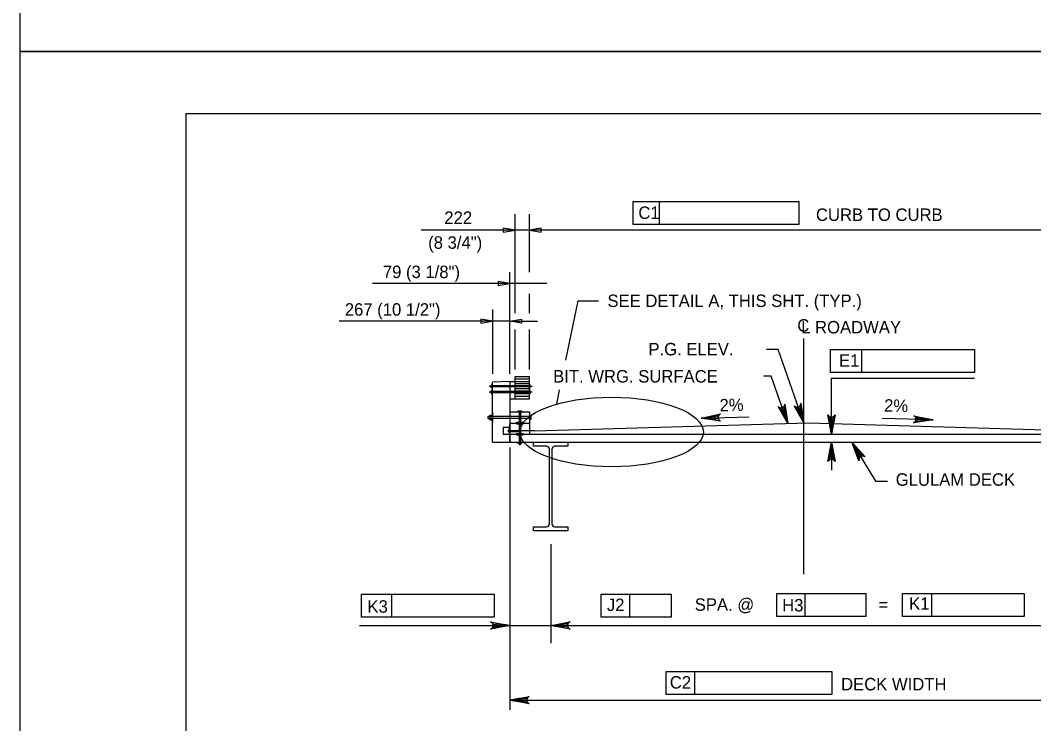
# Model space of a CAD drawing. Extents: x 638175 to 640495, y 294277 to 298435.
# Drawn here: x 638435.5 to 638679.7, y 296491.5 to 296661 of the extents above; entities that cross this region are included whole.
import ezdxf

# ---------------------------------------------------------------- set-up
doc = ezdxf.new("R2010")
doc.units = 0
for name, color, linetype in [('2', 7, 'Continuous'), ('3', 7, 'Continuous'), ('4', 7, 'Continuous'), ('6', 7, 'Continuous'), ('PLT-BNDY', 7, 'Continuous')]:
    doc.layers.add(name, color=color, linetype=linetype)

msp = doc.modelspace()

# ---------------------------------------------------------------- linework, layer by layer
at = {"layer": '2'}
for p, q in [((638475.46, 296074.46), (638475.46, 296638.46)), ((638475.46, 296638.46), (639261.46, 296638.46)), ((638554.69, 296590.38), (638554.69, 296614.24)), ((638558.16, 296600.26), (638558.16, 296614.24)), ((638560.6, 296610.39), (638532.11, 296610.39)), ((638686.45, 296610.39), (638559.36, 296610.39)), ((638553.45, 296575.77), (638553.45, 296600.26)), ((638562.36, 296597.55), (638520.38, 296597.55)), ((638558.16, 296590.38), (638558.16, 296595.03)), ((638549.28, 296591.29), (638549.28, 296575.77)), ((638553.45, 296588.49), (638512.31, 296588.49)), ((638553.45, 296588.49), (638560.11, 296588.49)), ((638554.69, 296576.86), (638554.69, 296586.46)), ((638558.16, 296576.86), (638558.16, 296586.46)), ((638624.32, 296527.56), (638624.32, 296584.32)), ((638554.69, 296569.78), (638554.69, 296575.14)), ((638554.69, 296575.14), (638558.16, 296575.14)), ((638554.69, 296574.55), (638558.16, 296574.55)), ((638558.16, 296569.78), (638558.16, 296575.14)), ((638630.96, 296574.77), (638665.42, 296574.77)), ((638630.96, 296561.25), (638630.96, 296574.77)), ((638548.75, 296572.88), (638548.77, 296572.91)), ((638548.75, 296572.88), (638548.75, 296572.63)), ((638548.75, 296572.63), (638548.77, 296572.61)), ((638548.95, 296572.91), (638548.77, 296572.91)), ((638548.95, 296572.61), (638548.77, 296572.61)), ((638548.95, 296572.93), (638548.95, 296572.59)), ((638548.95, 296572.93), (638548.95, 296572.59)), ((638548.99, 296572.99), (638549.19, 296572.99)), ((638548.99, 296572.87), (638549.19, 296572.87)), ((638548.99, 296572.64), (638549.19, 296572.64)), ((638548.99, 296572.53), (638549.19, 296572.53)), ((638549.19, 296572.17), (638549.19, 296573.36)), ((638549.19, 296573.36), (638549.28, 296573.36)), ((638549.19, 296572.53), (638549.19, 296572.99)), ((638549.28, 296572.17), (638549.19, 296572.17)), ((638549.19, 296572.17), (638549.19, 296572.17)), ((638549.19, 296570.77), (638549.19, 296571.97)), ((638549.19, 296571.97), (638549.28, 296571.97)), ((638553.45, 296573.95), (638549.28, 296573.76)), ((638549.28, 296559.29), (638549.28, 296573.76)), ((638558.16, 296572.91), (638549.28, 296572.91)), ((638558.16, 296572.62), (638549.28, 296572.62)), ((638549.28, 296572.17), (638549.28, 296572.17)), ((638553.45, 296573.95), (638554.69, 296573.95)), ((638553.45, 296573.95), (638553.45, 296566.61)), ((638554.69, 296573.95), (638558.16, 296573.95)), ((638558.16, 296573.36), (638554.69, 296573.36)), ((638558.16, 296572.17), (638554.69, 296572.17)), ((638548.75, 296571.5), (638548.77, 296571.52)), ((638548.75, 296571.5), (638548.75, 296571.25)), ((638548.75, 296571.25), (638548.77, 296571.22)), ((638548.95, 296571.52), (638548.77, 296571.52)), ((638548.95, 296571.22), (638548.77, 296571.22)), ((638548.95, 296571.54), (638548.95, 296571.2)), ((638548.95, 296571.54), (638548.95, 296571.2)), ((638548.99, 296571.6), (638549.19, 296571.6)), ((638548.99, 296571.48), (638549.19, 296571.48)), ((638548.99, 296571.25), (638549.19, 296571.25)), ((638548.99, 296571.14), (638549.19, 296571.14)), ((638549.19, 296571.14), (638549.19, 296571.6)), ((638549.28, 296570.77), (638549.19, 296570.77)), ((638549.19, 296570.77), (638549.19, 296570.77)), ((638558.16, 296571.52), (638549.28, 296571.52)), ((638558.16, 296571.22), (638549.28, 296571.22)), ((638549.28, 296570.77), (638549.28, 296570.77)), ((638553.45, 296569.78), (638558.16, 296569.78)), ((638558.16, 296571.57), (638554.69, 296571.57)), ((638558.16, 296570.98), (638554.69, 296570.98)), ((638554.69, 296570.38), (638558.16, 296570.38)), ((638555.83, 296558.78), (638555.83, 296566.96)), ((638548.15, 296565.47), (638548.2, 296565.51)), ((638548.15, 296565.47), (638548.15, 296565.07)), ((638548.15, 296565.07), (638548.2, 296565.02)), ((638548.6, 296565.51), (638548.2, 296565.51)), ((638548.2, 296565.02), (638548.6, 296565.02)), ((638548.6, 296564.86), (638548.6, 296565.68)), ((638548.6, 296565.51), (638548.6, 296565.51)), ((638548.69, 296565.82), (638549.18, 296565.82)), ((638548.69, 296565.54), (638549.18, 296565.54)), ((638548.69, 296565), (638549.18, 296565)), ((638548.7, 296564.72), (638549.18, 296564.72)), ((638549.18, 296566.46), (638549.18, 296564.08)), ((638549.28, 296566.46), (638549.18, 296566.46)), ((638549.18, 296565.82), (638549.18, 296564.72)), ((638549.28, 296565.54), (638549.18, 296565.54)), ((638549.28, 296565), (638549.18, 296565)), ((638549.28, 296566.46), (638549.28, 296564.08)), ((638558.21, 296565.51), (638549.28, 296565.51)), ((638558.21, 296565.02), (638549.28, 296565.02)), ((638553.45, 296566.61), (638553.45, 296563.93)), ((638553.45, 296566.61), (638558.21, 296566.61)), ((638555.68, 296566.61), (638555.68, 296559.29)), ((638555.98, 296566.61), (638555.98, 296559.29)), ((638558.21, 296566.61), (638558.21, 296563.93)), ((638599.57, 296565.13), (638611.11, 296565.43)), ((638655.43, 296564.69), (638643.19, 296565.03)), ((638549.18, 296564.08), (638549.28, 296564.08)), ((638551.86, 296562.84), (638551.86, 296561.25)), ((638553.45, 296562.84), (638551.86, 296562.84)), ((638553.21, 296562.24), (638553.06, 296562.24)), ((638553.06, 296562.24), (638553.06, 296561.85)), ((638553.21, 296562.34), (638553.26, 296562.34)), ((638553.21, 296562.34), (638553.21, 296561.74)), ((638553.26, 296562.84), (638553.26, 296561.25)), ((638553.26, 296562.16), (638555.38, 296562.16)), ((638553.45, 296563.93), (638553.45, 296561.25)), ((638553.45, 296563.93), (638558.21, 296563.93)), ((638558.21, 296562.06), (638553.45, 296562.06)), ((638555.04, 296564.13), (638555.04, 296563.73)), ((638555.04, 296564.13), (638556.62, 296564.13)), ((638555.04, 296563.73), (638556.62, 296563.73)), ((638555.59, 296562.04), (638555.38, 296562.16)), ((638555.59, 296562.04), (638555.38, 296561.91)), ((638556.62, 296564.13), (638556.62, 296563.73)), ((638558.21, 296563.93), (638558.21, 296561.25)), ((638559.41, 296562.06), (638558.21, 296562.06)), ((638551.86, 296561.25), (638553.45, 296561.25)), ((638553.21, 296561.85), (638553.06, 296561.85)), ((638553.21, 296561.74), (638553.26, 296561.74)), ((638553.26, 296561.91), (638555.38, 296561.91)), ((638553.45, 296561.25), (638553.45, 296559.29)), ((638555.04, 296561.45), (638555.04, 296561.05)), ((638555.04, 296561.45), (638556.62, 296561.45)), ((638555.04, 296561.05), (638556.62, 296561.05)), ((638556.62, 296561.45), (638556.62, 296561.05)), ((638553.45, 296558.01), (638553.45, 296494.83)), ((638555.23, 296559.29), (638555.23, 296559.29)), ((638555.23, 296559.29), (638555.23, 296559.19)), ((638555.23, 296559.2), (638555.23, 296559.2)), ((638555.23, 296559.19), (638556.43, 296559.19)), ((638555.6, 296558.99), (638555.6, 296559.19)), ((638555.65, 296559.29), (638555.65, 296559.19)), ((638556, 296558.96), (638555.66, 296558.96)), ((638555.68, 296558.96), (638555.68, 296558.78)), ((638555.7, 296558.76), (638555.68, 296558.78)), ((638555.7, 296558.93), (638555.95, 296558.93)), ((638555.7, 296558.91), (638555.95, 296558.91)), ((638555.7, 296558.88), (638555.95, 296558.88)), ((638555.7, 296558.86), (638555.95, 296558.86)), ((638555.7, 296558.83), (638555.95, 296558.83)), ((638555.7, 296558.8), (638555.95, 296558.8)), ((638555.7, 296558.78), (638555.95, 296558.78)), ((638555.95, 296558.76), (638555.7, 296558.76)), ((638555.72, 296558.99), (638555.72, 296559.19)), ((638555.95, 296558.99), (638555.95, 296559.19)), ((638555.95, 296558.76), (638555.98, 296558.78)), ((638555.98, 296558.96), (638555.98, 296558.78)), ((638556, 296559.29), (638556, 296559.19)), ((638556.06, 296558.99), (638556.06, 296559.19)), ((638556.43, 296559.19), (638556.43, 296559.29)), ((638630.98, 296559.29), (638630.98, 296552.6)), ((638563.3, 296534.79), (638563.3, 296512.32)), ((638563.3, 296521.08), (638563.3, 296510.92)), ((638517.21, 296515.17), (638553.45, 296515.17)), ((638553.45, 296515.17), (638688.41, 296515.17)), ((638553.45, 296497.2), (638695.18, 296497.2))]:
    msp.add_line(p, q, dxfattribs=at)
for points in [[(638551.86, 296610.86), (638551.86, 296609.92), (638554.69, 296610.39)], [(638550.62, 296598.02), (638550.62, 296597.07), (638553.45, 296597.55)], [(638546.45, 296588.96), (638546.45, 296588.01), (638549.28, 296588.49)], [(638556.29, 296588.96), (638556.29, 296588.01), (638553.45, 296588.49)], [(638602.94, 296564.74), (638602.92, 296565.69), (638600.09, 296565.14)], [(638651.34, 296565.28), (638651.32, 296564.34), (638654.16, 296564.73)], [(638631.43, 296564.25), (638630.49, 296564.25), (638630.96, 296561.42)], [(638630.51, 296556.36), (638631.45, 296556.36), (638630.98, 296559.2)], [(638566.13, 296515.64), (638566.13, 296514.7), (638563.3, 296515.17)], [(638556.08, 296496.76), (638556.08, 296497.63), (638553.45, 296497.2)]]:
    msp.add_lwpolyline(points, close=True, dxfattribs=at)
for points in [[(638620.45, 296563.82), (638618.08, 296567.93), (638618.43, 296567.67), (638618.79, 296567.6), (638619.1, 296567.65), (638619.38, 296567.81), (638619.61, 296568.08), (638619.73, 296568.51), (638620.45, 296563.82), (638619.61, 296568.08), (638619.38, 296567.81), (638620.45, 296563.82), (638619.1, 296567.65), (638618.79, 296567.6), (638620.45, 296563.82), (638618.43, 296567.67)], [(638624.3, 296563.99), (638621.93, 296568.1), (638622.28, 296567.84), (638622.64, 296567.77), (638622.95, 296567.82), (638623.23, 296567.98), (638623.46, 296568.25), (638623.58, 296568.68), (638624.3, 296563.99), (638623.46, 296568.25), (638623.23, 296567.98), (638624.3, 296563.99), (638622.95, 296567.82), (638622.64, 296567.77), (638624.3, 296563.99), (638622.28, 296567.84)], [(638599.57, 296565.13), (638604.2, 296566.12), (638603.85, 296565.87), (638603.67, 296565.55), (638603.63, 296565.24), (638603.69, 296564.92), (638603.88, 296564.62), (638604.25, 296564.38), (638599.57, 296565.13), (638603.88, 296564.62), (638603.69, 296564.92), (638599.57, 296565.13), (638603.63, 296565.24), (638603.67, 296565.55), (638599.57, 296565.13), (638603.85, 296565.87)], [(638630.96, 296561.25), (638630.09, 296565.91), (638630.33, 296565.55), (638630.65, 296565.37), (638630.96, 296565.31), (638631.27, 296565.37), (638631.58, 296565.55), (638631.83, 296565.91), (638630.96, 296561.25), (638631.58, 296565.55), (638631.27, 296565.37), (638630.96, 296561.25), (638630.96, 296565.31), (638630.65, 296565.37), (638630.96, 296561.25), (638630.33, 296565.55)], [(638655.43, 296564.69), (638650.74, 296563.95), (638651.11, 296564.19), (638651.3, 296564.49), (638651.37, 296564.8), (638651.32, 296565.12), (638651.15, 296565.44), (638650.79, 296565.7), (638655.43, 296564.69), (638651.15, 296565.44), (638651.32, 296565.12), (638655.43, 296564.69), (638651.37, 296564.8), (638651.3, 296564.49), (638655.43, 296564.69), (638651.11, 296564.19)], [(638630.98, 296559.29), (638631.85, 296554.63), (638631.61, 296554.98), (638631.29, 296555.17), (638630.98, 296555.22), (638630.67, 296555.17), (638630.36, 296554.98), (638630.11, 296554.63), (638630.98, 296559.29), (638630.36, 296554.98), (638630.67, 296555.17), (638630.98, 296559.29), (638630.98, 296555.22), (638631.29, 296555.17), (638630.98, 296559.29), (638631.61, 296554.98)], [(638635.88, 296559.29), (638639.06, 296555.77), (638638.66, 296555.94), (638638.3, 296555.94), (638638, 296555.82), (638637.76, 296555.61), (638637.59, 296555.29), (638637.57, 296554.85), (638635.88, 296559.29), (638637.59, 296555.29), (638637.76, 296555.61), (638635.88, 296559.29), (638638, 296555.82), (638638.3, 296555.94), (638635.88, 296559.29), (638638.66, 296555.94)], [(638553.45, 296515.17), (638548.79, 296514.3), (638549.15, 296514.55), (638549.33, 296514.86), (638549.39, 296515.17), (638549.33, 296515.48), (638549.15, 296515.8), (638548.79, 296516.04), (638553.45, 296515.17), (638549.15, 296515.8), (638549.33, 296515.48), (638553.45, 296515.17), (638549.39, 296515.17), (638549.33, 296514.86), (638553.45, 296515.17), (638549.15, 296514.55)], [(638563.3, 296515.17), (638567.96, 296516.04), (638567.6, 296515.8), (638567.41, 296515.48), (638567.36, 296515.17), (638567.41, 296514.86), (638567.6, 296514.55), (638567.96, 296514.3), (638563.3, 296515.17), (638567.6, 296514.55), (638567.41, 296514.86), (638563.3, 296515.17), (638567.36, 296515.17), (638567.41, 296515.48), (638563.3, 296515.17), (638567.6, 296515.8)], [(638553.45, 296497.2), (638558.11, 296498.07), (638557.75, 296497.82), (638557.57, 296497.51), (638557.51, 296497.2), (638557.57, 296496.88), (638557.75, 296496.57), (638558.11, 296496.32), (638553.45, 296497.2), (638557.75, 296496.57), (638557.57, 296496.88), (638553.45, 296497.2), (638557.51, 296497.2), (638557.57, 296497.51), (638553.45, 296497.2), (638557.75, 296497.82)]]:
    msp.add_lwpolyline(points, dxfattribs=at)
for centre, radius, start, end in [((638549.02, 296572.93), 0.0634, 114.702, 244.7086), ((638549.15, 296572.76), 0.195, 144.5002, 216.0965), ((638549.02, 296572.59), 0.0631, 114.1235, 245.2701), ((638557.49, 296572.76), 0.898, 318.5212, 41.4788), ((638557.49, 296571.37), 0.898, 318.5212, 41.4788), ((638549.02, 296571.54), 0.0634, 114.702, 244.7086), ((638549.15, 296571.37), 0.195, 144.5002, 216.0965), ((638549.02, 296571.2), 0.0631, 114.1235, 245.2701), ((638548.75, 296565.68), 0.151, 113.4078, 245.8697), ((638549.07, 296565.27), 0.469, 143.8906, 215.5087), ((638548.75, 296564.86), 0.152, 115.2831, 249.0228), ((638555.83, 296565.93), 0.898, 48.5212, 131.4788), ((638557.75, 296565.27), 0.852, 303.2799, 56.719), ((638555.66, 296559.02), 0.0631, 204.7299, 335.8765), ((638555.83, 296559.15), 0.195, 233.9035, 305.4998), ((638556, 296559.02), 0.0634, 205.2914, 335.298)]:
    msp.add_arc(centre, radius, start, end, dxfattribs=at)
at = {"layer": '3'}
for p, q in [((638558.79, 296572.76), (638548.48, 296572.76)), ((638553.45, 296573.95), (638553.45, 296559.29)), ((638558.79, 296571.38), (638548.48, 296571.38)), ((638553.45, 296559.29), (638553.45, 296563.71)), ((638559.36, 296562.07), (638625.3, 296563.96)), ((638625.3, 296563.96), (638690.42, 296562.04)), ((638553.45, 296561.25), (638695.18, 296561.25)), ((638549.28, 296559.29), (638699.35, 296559.29)), ((638553.45, 296559.29), (638553.45, 296559.29)), ((638561.25, 296559.29), (638565.35, 296559.29)), ((638563.01, 296539.66), (638563.01, 296557.63)), ((638563.58, 296557.63), (638563.58, 296539.66))]:
    msp.add_line(p, q, dxfattribs=at)
for points in [[(638562.27, 296558.37), (638559.15, 296558.37), (638559.15, 296559.29), (638567.44, 296559.29), (638567.44, 296558.37), (638564.32, 296558.37)], [(638559.15, 296538), (638559.15, 296538.92), (638562.27, 296538.92)], [(638564.32, 296538.92), (638567.44, 296538.92), (638567.44, 296538), (638559.15, 296538)]]:
    msp.add_lwpolyline(points, dxfattribs=at)
for centre, start, end in [((638562.27, 296557.63), 0, 90), ((638564.32, 296557.63), 90, 180), ((638562.27, 296539.66), 270, 0), ((638564.32, 296539.66), 180, 270)]:
    msp.add_arc(centre, 0.738, start, end, dxfattribs=at)
at = {"layer": '4'}
for p, q in [((638583.19, 296617.26), (638623.05, 296617.26)), ((638583.19, 296611.72), (638583.19, 296617.26)), ((638589.52, 296611.72), (638589.52, 296617.26)), ((638623.05, 296617.26), (638623.05, 296611.72)), ((638623.05, 296611.72), (638583.19, 296611.72)), ((638566.93, 296579.04), (638569.9, 296593.35)), ((638569.91, 296593.35), (638574.82, 296593.35)), ((638618.11, 296581.61), (638615.27, 296581.61)), ((638624.3, 296563.99), (638618.11, 296581.61)), ((638630.75, 296581.68), (638665.46, 296581.68)), ((638630.75, 296576.14), (638630.75, 296581.68)), ((638638.25, 296576.14), (638638.25, 296581.68)), ((638665.46, 296581.68), (638665.46, 296576.14)), ((638616.44, 296575.23), (638614.54, 296575.23)), ((638620.45, 296563.82), (638616.44, 296575.23)), ((638665.46, 296576.14), (638630.75, 296576.14)), ((638564.74, 296568.48), (638565.45, 296571.91)), ((638635.88, 296559.29), (638641.6, 296549.95)), ((638641.6, 296549.95), (638644.43, 296549.95)), ((638517.72, 296522.74), (638549.68, 296522.74)), ((638517.72, 296517.2), (638517.72, 296522.74)), ((638525, 296517.2), (638525, 296522.74)), ((638549.68, 296522.74), (638549.68, 296517.2)), ((638575.48, 296522.74), (638592.36, 296522.74)), ((638575.48, 296517.2), (638575.48, 296522.74)), ((638582.37, 296517.2), (638582.37, 296522.74)), ((638592.36, 296522.74), (638592.36, 296517.2)), ((638617.75, 296522.85), (638639.24, 296522.85)), ((638617.75, 296517.31), (638617.75, 296522.85)), ((638624.64, 296517.31), (638624.64, 296522.85)), ((638639.24, 296522.85), (638639.24, 296517.31)), ((638648.1, 296522.85), (638677.4, 296522.85)), ((638648.1, 296517.31), (638648.1, 296522.85)), ((638655.15, 296517.31), (638655.15, 296522.85)), ((638677.4, 296522.85), (638677.4, 296517.31)), ((638549.68, 296517.2), (638517.72, 296517.2)), ((638592.36, 296517.2), (638575.48, 296517.2)), ((638639.24, 296517.31), (638617.75, 296517.31)), ((638677.4, 296517.31), (638648.1, 296517.31)), ((638591.15, 296504.06), (638631.01, 296504.06)), ((638591.15, 296498.52), (638591.15, 296504.06)), ((638598.04, 296498.52), (638598.04, 296504.06)), ((638631.01, 296504.06), (638631.01, 296498.52)), ((638631.01, 296498.52), (638591.15, 296498.52))]:
    msp.add_line(p, q, dxfattribs=at)
for points in [[(638619.96, 296566.65), (638619.06, 296566.34), (638620.45, 296563.82)], [(638623.82, 296566.76), (638622.93, 296566.45), (638624.32, 296563.93)], [(638636.96, 296556.62), (638637.76, 296557.11), (638635.88, 296559.29)]]:
    msp.add_lwpolyline(points, close=True, dxfattribs=at)
msp.add_ellipse((638577.97, 296561.77), major_axis=(-22.11, 0), ratio=0.378749, dxfattribs=at)
at = {"layer": '6'}
msp.add_lwpolyline([(638560.99, 296609.92), (638560.99, 296610.86), (638558.16, 296610.39)], close=True, dxfattribs=at)
at = {"layer": 'PLT-BNDY'}
for points in [[(638435.46, 297247.46), (639276.46, 297247.46), (639276.46, 296653.46), (638435.46, 296653.46)], [(638435.46, 296653.46), (639276.46, 296653.46), (639276.46, 296059.46), (638435.46, 296059.46)]]:
    msp.add_lwpolyline(points, close=True, dxfattribs=at)

# ---------------------------------------------------------------- texts
at = {"layer": '4'}
for s, p in [('C1', (638584.41, 296613.1)), ('222', (638537.65, 296611.91)), ('CURB TO CURB', (638627.22, 296612.62)), ('(8 3/4")', (638533.76, 296605.91)), ('79 (3 1/8")', (638522.84, 296598.85)), ('SEE DETAIL A, THIS SHT. (TYP.)', (638576.97, 296591.88)), ('267 (10 1/2")', (638513.67, 296589.79)), ('C', (638622.72, 296585.95)), ('L ROADWAY', (638623.65, 296585.52)), ('P.G. ELEV.', (638586.84, 296580.23)), ('E1', (638632.76, 296577.48)), ('BIT. WRG. SURFACE', (638563.88, 296573.69)), ('GLULAM DECK', (638646.44, 296548.82)), ('K3', (638519.13, 296518.24)), ('J2', (638576.82, 296518.64)), ('SPA. @', (638598.01, 296518.7)), ('H3', (638619.07, 296518.54)), ('=', (638642.3, 296518.7)), ('K1', (638649.67, 296518.94)), ('C2', (638592, 296499.96)), ('DECK WIDTH', (638633.27, 296499.53))]:
    msp.add_text(s, height=3, dxfattribs=at).set_placement(p)
for rotation, p in [(1.5039, (638604.02, 296566.71)), (358.4961, (638643.6, 296566.7))]:
    msp.add_text('2%', height=3, rotation=rotation, dxfattribs=at).set_placement(p)

doc.saveas('drawing.dxf')
